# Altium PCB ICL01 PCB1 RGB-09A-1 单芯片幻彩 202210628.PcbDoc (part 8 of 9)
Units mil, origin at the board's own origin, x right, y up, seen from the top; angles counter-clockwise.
Board outline 17436.43 x 6581.89 mil, 2 copper layers (Top Layer, Bottom Layer), stack 65.792 mil thick; 425 components, 516 nets, 1625 pads, 2772 vias.
Unrouted connection lines stored in the file: 1.
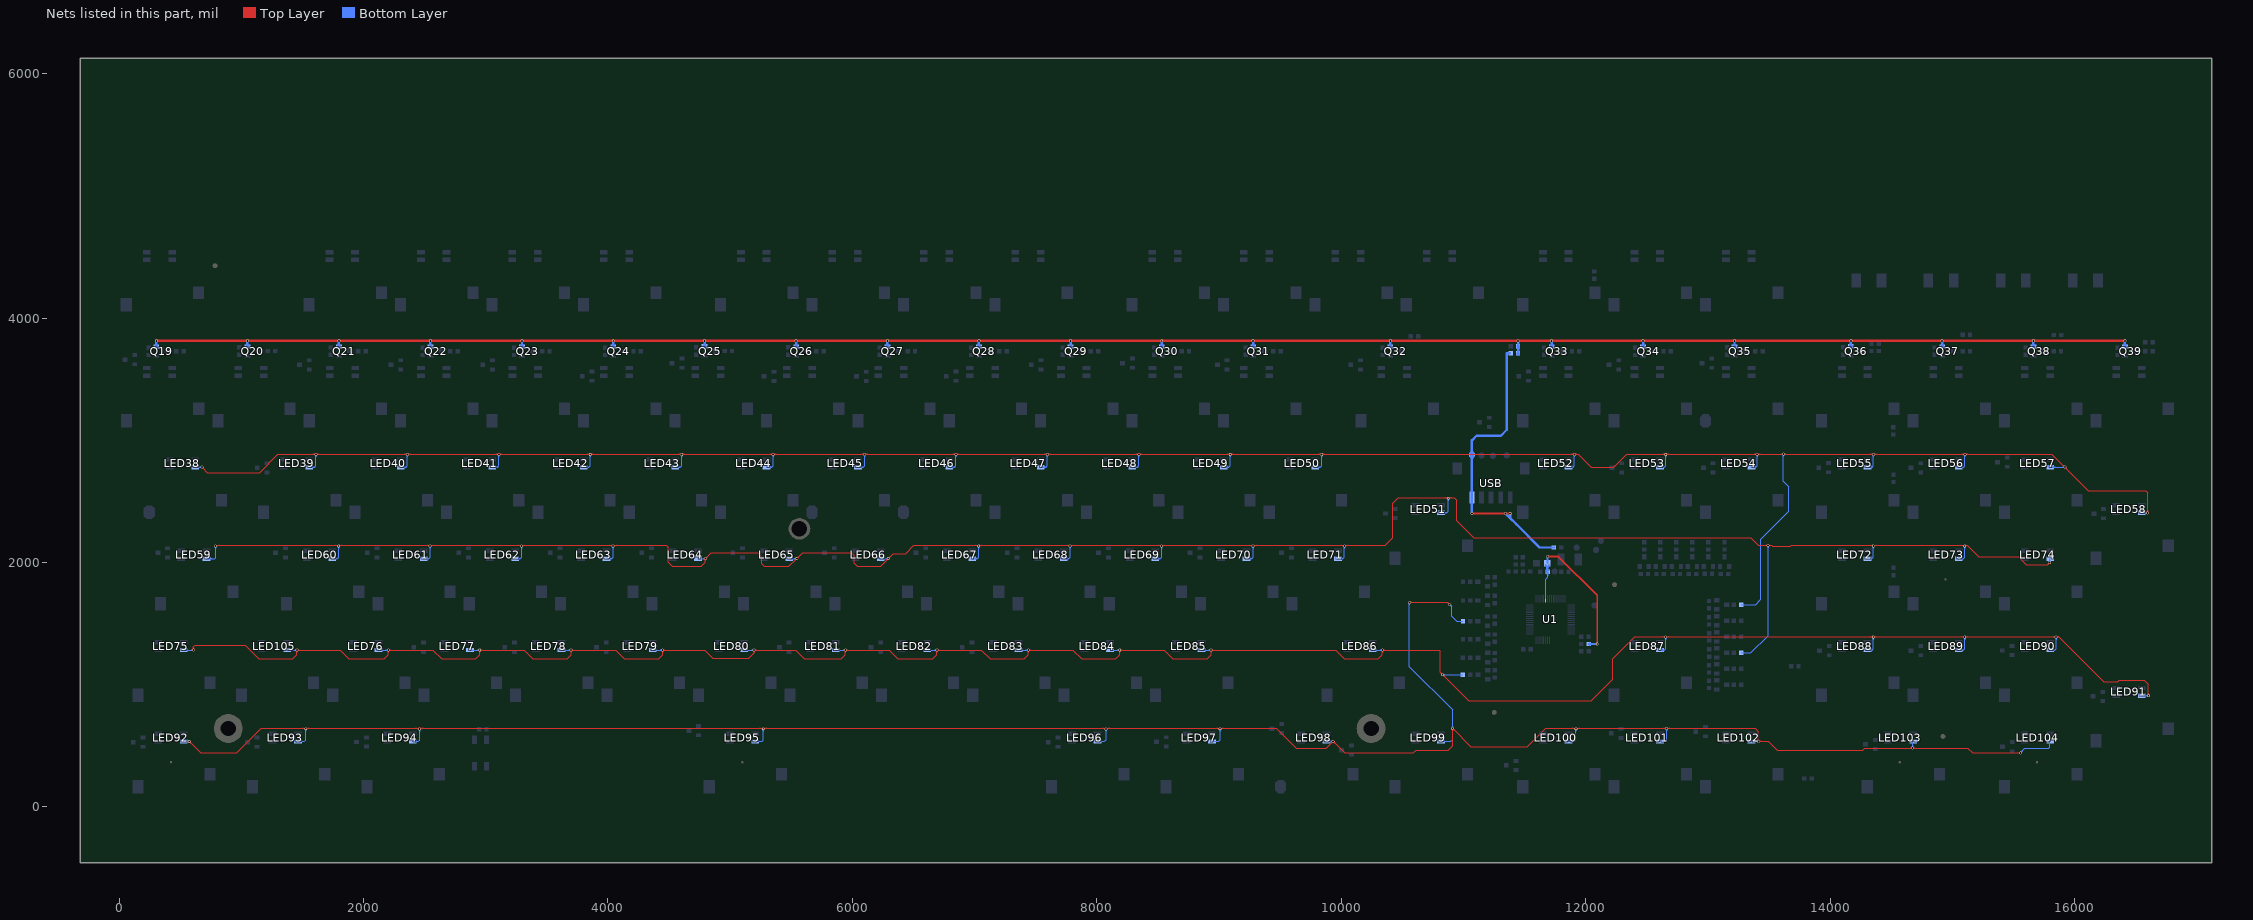
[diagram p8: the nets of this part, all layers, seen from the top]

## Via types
v1: diameter 23.62, hole 15.75, Top Layer to Bottom Layer, tented both sides, 2766 vias
v2: diameter 19.68, hole 11.81, Top Layer to Bottom Layer, tented both sides, 6 vias

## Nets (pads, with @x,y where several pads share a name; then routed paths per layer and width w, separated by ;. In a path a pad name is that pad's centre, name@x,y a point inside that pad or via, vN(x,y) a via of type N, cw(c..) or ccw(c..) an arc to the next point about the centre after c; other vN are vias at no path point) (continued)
RED2: LED38.R LED39.R LED40.R LED41.R LED42.R LED43.R LED44.R LED45.R LED46.R LED47.R LED48.R LED49.R LED50.R LED52.R LED53.R LED54.R LED55.R LED56.R LED57.R LED58.R RR7.2 | length 23323.4
  Top Layer w7.87: v1@680.32,2771.85 cw(c680.32,2752.84) 693.77,2766.28 cw(c707.21,2779.73) v1@688.2,2779.73 ; v1(680.32,2779.73) 723.96,2736.09 1149.71,2736.09 1300.78,2887.16 v1@11906.84,2887.16 ; 1587.12,2887.16 cw(c1587.12,2860.47) v1@1605.99,2879.34 ; 1597.98,2887.16 ccw(c1597.98,2898.49) v1@1605.99,2890.48 ; v1@1617.13,2879.34 cw(c1636,2860.47) 1636,2887.16 ; v1@1617.13,2890.48 ccw(c1625.14,2898.49) 1625.14,2887.16 ; 2335.15,2887.16 cw(c2335.15,2860.47) v1@2354.03,2879.34 ; 2346.01,2887.16 ccw(c2346.01,2898.49) v1@2354.03,2890.48 ; v1@2365.16,2879.34 cw(c2384.03,2860.47) 2384.03,2887.16 ; v1@2365.16,2890.48 ccw(c2373.17,2898.49) 2373.17,2887.16 ; 3083.18,2887.16 cw(c3083.18,2860.47) v1@3102.06,2879.34 ; 3094.05,2887.16 ccw(c3094.05,2898.49) v1@3102.06,2890.48 ; v1@3113.19,2879.34 cw(c3132.06,2860.47) 3132.06,2887.16 ; v1@3113.19,2890.48 ccw(c3121.2,2898.49) 3121.2,2887.16 ; 3831.22,2887.16 cw(c3831.22,2860.47) v1@3850.09,2879.34 ; 3842.08,2887.16 ccw(c3842.08,2898.49) v1@3850.09,2890.48 ; v1@3861.22,2879.34 cw(c3880.1,2860.47) 3880.1,2887.16 ; v1@3861.22,2890.48 ccw(c3869.23,2898.49) 3869.23,2887.16 ; 4579.25,2887.16 cw(c4579.25,2860.47) v1@4598.12,2879.34 ; 4590.11,2887.16 ccw(c4590.11,2898.49) v1@4598.12,2890.48 ; v1@4609.26,2879.34 cw(c4628.13,2860.47) 4628.13,2887.16 ; v1@4609.26,2890.48 ccw(c4617.27,2898.49) 4617.27,2887.16 ; 5327.28,2887.16 cw(c5327.28,2860.47) v1@5346.15,2879.34 ; 5338.14,2887.16 ccw(c5338.14,2898.49) v1@5346.15,2890.48 ; v1@5357.29,2879.34 cw(c5376.16,2860.47) 5376.16,2887.16 ; v1@5357.29,2890.48 ccw(c5365.3,2898.49) 5365.3,2887.16 ; 6075.31,2887.16 cw(c6075.31,2860.47) v1@6094.18,2879.34 ; 6086.17,2887.16 ccw(c6086.17,2898.49) v1@6094.18,2890.48 ; v1@6105.32,2879.34 cw(c6124.19,2860.47) 6124.19,2887.16 ; v1@6105.32,2890.48 ccw(c6113.33,2898.49) 6113.33,2887.16 ; 6823.34,2887.16 cw(c6823.34,2860.47) v1@6842.21,2879.34 ; 6834.2,2887.16 ccw(c6834.2,2898.49) v1@6842.21,2890.48 ; v1@6853.35,2879.34 cw(c6872.22,2860.47) 6872.22,2887.16 ; v1@6853.35,2890.48 ccw(c6861.36,2898.49) 6861.36,2887.16 ; 7571.37,2887.16 cw(c7571.37,2860.47) v1@7590.25,2879.34 ; 7582.23,2887.16 ccw(c7582.23,2898.49) v1@7590.25,2890.48 ; v1@7601.38,2879.34 cw(c7620.25,2860.47) 7620.25,2887.16 ; v1@7601.38,2890.48 ccw(c7609.39,2898.49) 7609.39,2887.16 ; 8319.4,2887.16 cw(c8319.4,2860.47) v1@8338.28,2879.34 ; 8330.27,2887.16 ccw(c8330.27,2898.49) v1@8338.28,2890.48 ; v1@8349.41,2879.34 cw(c8368.29,2860.47) 8368.29,2887.16 ; v1@8349.41,2890.48 ccw(c8357.42,2898.49) 8357.42,2887.16 ; 9067.44,2887.16 cw(c9067.44,2860.47) v1@9086.31,2879.34 ; 9078.3,2887.16 ccw(c9078.3,2898.49) v1@9086.31,2890.48 ; v1@9097.44,2879.34 cw(c9116.32,2860.47) 9116.32,2887.16 ; v1@9097.44,2890.48 ccw(c9105.45,2898.49) 9105.45,2887.16 ; 9815.47,2887.16 cw(c9815.47,2860.47) v1@9834.34,2879.34 ; 9826.33,2887.16 ccw(c9826.33,2898.49) v1@9834.34,2890.48 ; v1@9845.48,2879.34 cw(c9864.35,2860.47) 9864.35,2887.16 ; v1@9845.48,2890.48 ccw(c9853.49,2898.49) 9853.49,2887.16 ; 11882.4,2887.16 cw(c11882.4,2860.47) v1@11901.27,2879.34 ; 11893.26,2887.16 ccw(c11893.26,2898.49) v1@11901.27,2890.48 ; v1(11906.84,2884.91) 11939.02,2884.91 12045.44,2778.49 12227.84,2778.49 12336.5,2887.16 13617.79,2887.16 v1(13618.05,2886.9) 15813.44,2886.9 v1@15920.65,2779.69 ; v1@11912.41,2879.34 cw(c11925.85,2865.9) 11925.85,2884.91 cw(c11925.85,2903.92) v1@11912.41,2890.48 ; 12630.43,2887.16 cw(c12630.43,2860.47) v1@12649.3,2879.34 ; 12641.29,2887.16 ccw(c12641.29,2898.49) v1@12649.3,2890.48 ; v1@12660.44,2879.34 cw(c12679.31,2860.47) 12679.31,2887.16 ; v1@12660.44,2890.48 ccw(c12668.45,2898.49) 12668.45,2887.16 ; 13378.46,2887.16 cw(c13378.46,2860.47) v1@13397.33,2879.34 ; 13389.32,2887.16 ccw(c13389.32,2898.49) v1@13397.33,2890.48 ; v1@13408.47,2879.34 cw(c13427.34,2860.47) 13427.34,2887.16 ; v1@13408.47,2890.48 ccw(c13416.48,2898.49) 13416.48,2887.16 ; 13598.42,2887.16 cw(c13598.42,2867.28) v1@13612.48,2881.34 ; 13599.66,2887.16 ccw(c13599.66,2905.3) v1@13612.48,2892.47 ; v1@13623.62,2881.34 cw(c13637.06,2867.89) 13637.06,2886.9 cw(c13637.06,2905.91) v1@13623.62,2892.47 ; 14329.86,2886.9 cw(c14329.86,2861.09) v1@14348.12,2879.34 ; 14339.49,2886.9 ccw(c14339.49,2899.1) v1@14348.12,2890.48 ; v1@14359.26,2879.34 cw(c14377.51,2861.09) 14377.51,2886.9 ; v1@14359.26,2890.48 ccw(c14367.88,2899.1) 14367.88,2886.9 ; 15077.9,2886.9 cw(c15077.9,2861.09) v1@15096.15,2879.34 ; 15087.52,2886.9 ccw(c15087.52,2899.1) v1@15096.15,2890.48 ; v1@15107.29,2879.34 cw(c15125.54,2861.09) 15125.54,2886.9 ; v1@15107.29,2890.48 ccw(c15115.91,2899.1) 15115.91,2886.9 ; 15907.13,2793.21 ccw(c15920.68,2806.77) v1@15920.68,2787.6 ; 15907.29,2793.06 cw(c15893.96,2779.73) v1@15912.81,2779.73 ; v1@15920.68,2771.85 cw(c15920.68,2752.84) 15934.12,2766.28 cw(c15947.57,2779.73) v1@15928.56,2779.73 ; v1(15920.68,2779.73) 16112.05,2588.35 16580.42,2588.35 16596.64,2572.13 v1@16596.64,2405.71 ; v1@16591.15,2411.28 ccw(c16577.91,2424.53) 16596.64,2424.53 ; 16596.64,2424.91 ccw(c16615.92,2424.91) v1@16602.29,2411.28
  Bottom Layer w7.87: LED38.R@622.66,2779.73 v1(680.32,2779.73) ; v1@674.76,2774.16 ccw(c661.31,2760.72) 661.31,2779.73 ccw(c661.31,2798.74) v1@674.76,2785.29 ; LED39.R@1557.7,2779.73 1600.85,2779.73 ; LED39.R@1582.08,2770.92 cw(c1600.85,2755.31) 1600.85,2779.73 ; LED39.R@1582.08,2788.53 ccw(c1600.85,2804.14) 1600.85,2779.73 ; v1@1605.99,2879.34 cw(c1592.58,2865.93) 1611.55,2865.93 ; 1611.55,2865.87 cw(c1630.6,2865.87) v1@1617.13,2879.34 ; v1@1611.55,2886.39 1611.55,2790.42 1600.85,2779.73 ; LED40.R@2305.73,2779.73 2348.89,2779.73 ; LED40.R@2330.11,2770.92 cw(c2348.88,2755.31) 2348.88,2779.73 ; LED40.R@2330.11,2788.53 ccw(c2348.88,2804.14) 2348.88,2779.73 ; v1@2354.03,2879.34 cw(c2340.61,2865.93) 2359.58,2865.93 ; 2359.58,2865.87 cw(c2378.63,2865.87) v1@2365.16,2879.34 ; v1@2359.58,2886.39 2359.58,2790.42 2348.89,2779.73 ; LED41.R@3053.76,2779.73 3096.92,2779.73 ; LED41.R@3078.14,2770.92 cw(c3096.92,2755.31) 3096.92,2779.73 ; LED41.R@3078.14,2788.53 ccw(c3096.92,2804.14) 3096.92,2779.73 ; v1@3102.06,2879.34 cw(c3088.65,2865.93) 3107.61,2865.93 ; 3107.61,2865.87 cw(c3126.66,2865.87) v1@3113.19,2879.34 ; v1@3107.61,2886.39 3107.61,2790.42 3096.92,2779.73 ; LED42.R@3801.8,2779.73 3844.95,2779.73 ; LED42.R@3826.17,2770.92 cw(c3844.95,2755.31) 3844.95,2779.73 ; LED42.R@3826.17,2788.53 ccw(c3844.95,2804.14) 3844.95,2779.73 ; v1@3850.09,2879.34 cw(c3836.68,2865.93) 3855.64,2865.93 ; 3855.64,2865.87 cw(c3874.7,2865.87) v1@3861.22,2879.34 ; v1@3855.64,2886.39 3855.64,2790.42 3844.95,2779.73 ; LED43.R@4549.83,2779.73 4592.98,2779.73 ; LED43.R@4574.2,2770.92 cw(c4592.98,2755.31) 4592.98,2779.73 ; LED43.R@4574.2,2788.53 ccw(c4592.98,2804.14) 4592.98,2779.73 ; v1@4598.12,2879.34 cw(c4584.71,2865.93) 4603.67,2865.93 ; 4603.67,2865.87 cw(c4622.73,2865.87) v1@4609.26,2879.34 ; v1@4603.67,2886.39 4603.67,2790.42 4592.98,2779.73 ; LED44.R@5297.86,2779.73 5341.01,2779.73 ; LED44.R@5322.23,2770.92 cw(c5341.01,2755.31) 5341.01,2779.73 ; LED44.R@5322.23,2788.53 ccw(c5341.01,2804.14) 5341.01,2779.73 ; v1@5346.15,2879.34 cw(c5332.74,2865.93) 5351.71,2865.93 ; 5351.71,2865.87 cw(c5370.76,2865.87) v1@5357.29,2879.34 ; v1@5351.71,2886.39 5351.71,2790.42 5341.01,2779.73 ; LED45.R@6045.89,2779.73 6089.04,2779.73 ; LED45.R@6070.27,2770.92 cw(c6089.04,2755.31) 6089.04,2779.73 ; LED45.R@6070.27,2788.53 ccw(c6089.04,2804.14) 6089.04,2779.73 ; v1@6094.18,2879.34 cw(c6080.77,2865.93) 6099.74,2865.93 ; 6099.74,2865.87 cw(c6118.79,2865.87) v1@6105.32,2879.34 ; v1@6099.74,2886.39 6099.74,2790.42 6089.04,2779.73 ; LED46.R@6793.92,2779.73 6837.08,2779.73 ; LED46.R@6818.3,2770.92 cw(c6837.07,2755.31) 6837.07,2779.73 ; LED46.R@6818.3,2788.53 ccw(c6837.07,2804.14) 6837.07,2779.73 ; v1@6842.21,2879.34 cw(c6828.8,2865.93) 6847.77,2865.93 ; 6847.77,2865.87 cw(c6866.82,2865.87) v1@6853.35,2879.34 ; v1@6847.77,2886.39 6847.77,2790.42 6837.08,2779.73 ; LED47.R@7541.95,2779.73 7585.11,2779.73 ; LED47.R@7566.33,2770.92 cw(c7585.1,2755.31) 7585.1,2779.73 ; LED47.R@7566.33,2788.53 ccw(c7585.1,2804.14) 7585.1,2779.73 ; v1@7590.25,2879.34 cw(c7576.83,2865.93) 7595.8,2865.93 ; 7595.8,2865.87 cw(c7614.85,2865.87) v1@7601.38,2879.34 ; v1@7595.8,2886.39 7595.8,2790.42 7585.11,2779.73 ; LED48.R@8289.98,2779.73 8333.14,2779.73 ; LED48.R@8314.36,2770.92 cw(c8333.14,2755.31) 8333.14,2779.73 ; LED48.R@8314.36,2788.53 ccw(c8333.14,2804.14) 8333.14,2779.73 ; v1@8338.28,2879.34 cw(c8324.87,2865.93) 8343.83,2865.93 ; 8343.83,2865.87 cw(c8362.89,2865.87) v1@8349.41,2879.34 ; v1@8343.83,2886.39 8343.83,2790.42 8333.14,2779.73 ; LED49.R@9038.02,2779.73 9081.17,2779.73 ; LED49.R@9062.39,2770.92 cw(c9081.17,2755.31) 9081.17,2779.73 ; LED49.R@9062.39,2788.53 ccw(c9081.17,2804.14) 9081.17,2779.73 ; v1@9086.31,2879.34 cw(c9072.9,2865.93) 9091.86,2865.93 ; 9091.86,2865.87 cw(c9110.92,2865.87) v1@9097.44,2879.34 ; v1@9091.86,2886.39 9091.86,2790.42 9081.17,2779.73 ; LED50.R@9786.05,2779.73 9829.2,2779.73 ; LED50.R@9810.42,2770.92 cw(c9829.2,2755.31) 9829.2,2779.73 ; LED50.R@9810.42,2788.53 ccw(c9829.2,2804.14) 9829.2,2779.73 ; v1@9834.34,2879.34 cw(c9820.93,2865.93) 9839.9,2865.93 ; 9839.9,2865.87 cw(c9858.95,2865.87) v1@9845.48,2879.34 ; v1@9839.9,2886.39 9839.9,2790.42 9829.2,2779.73 ; LED52.R@11852.98,2779.73 11896.13,2779.73 11906.82,2790.42 v1@11906.82,2886.39 ; LED52.R@11877.35,2770.92 cw(c11896.13,2755.31) 11896.13,2779.73 cw(c11896.13,2804.14) LED52.R@11877.35,2788.53 ; v1@11901.27,2879.34 cw(c11887.86,2865.93) 11906.82,2865.93 ; 11906.82,2865.87 cw(c11925.88,2865.87) v1@11912.41,2879.34 ; LED53.R@12601.01,2779.73 12644.16,2779.73 ; LED53.R@12625.38,2770.92 cw(c12644.16,2755.31) 12644.16,2779.73 ; LED53.R@12625.38,2788.53 ccw(c12644.16,2804.14) 12644.16,2779.73 ; v1@12649.3,2879.34 cw(c12635.89,2865.93) 12654.86,2865.93 ; 12654.86,2865.87 cw(c12673.91,2865.87) v1@12660.44,2879.34 ; v1@12654.86,2886.39 12654.86,2790.42 12644.16,2779.73 ; RR7.2@13272.34,1654.53 13389.47,1654.53 13433.74,1698.79 13433.74,2190.36 13662.06,2418.68 13662.06,2619.52 13617.79,2663.79 v1@13617.79,2887.16 ; LED54.R@13349.04,2779.73 13392.19,2779.73 ; LED54.R@13373.42,2770.92 cw(c13392.19,2755.31) 13392.19,2779.73 ; LED54.R@13373.42,2788.53 ccw(c13392.19,2804.14) 13392.19,2779.73 ; v1@13397.33,2879.34 cw(c13383.92,2865.93) 13402.89,2865.93 ; 13402.89,2865.87 cw(c13421.94,2865.87) v1@13408.47,2879.34 ; v1@13402.89,2886.39 13402.89,2790.42 13392.19,2779.73 ; v1@13612.48,2881.34 cw(c13599.66,2868.51) 13617.79,2868.51 ; 13617.79,2867.28 cw(c13637.68,2867.28) v1@13623.62,2881.34 ; LED55.R@14299.83,2779.73 14342.98,2779.73 ; LED55.R@14324.2,2770.92 cw(c14342.98,2755.31) 14342.98,2779.73 ; LED55.R@14324.2,2788.53 ccw(c14342.98,2804.14) 14342.98,2779.73 ; v1@14348.12,2879.34 cw(c14334.71,2865.93) 14353.67,2865.93 ; 14353.67,2865.87 cw(c14372.73,2865.87) v1@14359.26,2879.34 ; v1@14353.67,2886.39 14353.67,2790.42 14342.98,2779.73 ; LED56.R@15047.86,2779.73 15091.01,2779.73 ; LED56.R@15072.23,2770.92 cw(c15091.01,2755.31) 15091.01,2779.73 ; LED56.R@15072.23,2788.53 ccw(c15091.01,2804.14) 15091.01,2779.73 ; v1@15096.15,2879.34 cw(c15082.74,2865.93) 15101.71,2865.93 ; 15101.71,2865.87 cw(c15120.76,2865.87) v1@15107.29,2879.34 ; v1@15101.71,2886.39 15101.71,2790.42 15091.01,2779.73 ; LED57.R@15795.89,2779.73 v1(15920.68,2779.73) ; LED57.R@15819.41,2769.98 cw(c15842.94,2746.46) 15842.94,2779.73 cw(c15842.94,2812.99) LED57.R@15819.41,2789.47 ; v1@15915.11,2774.16 ccw(c15901.67,2760.72) 15901.67,2779.73 ccw(c15901.67,2798.74) v1@15915.11,2785.29 ; LED58.R@16543.92,2405.71 v1(16596.72,2405.71) ; v1@16591.15,2400.14 ccw(c16577.71,2386.7) 16577.71,2405.71 ccw(c16577.71,2424.72) v1@16591.15,2411.28
  other v1: 1611.56,2884.91 2359.59,2884.91 3107.62,2884.91 3855.66,2884.91 4603.69,2884.91 5351.72,2884.91 6099.75,2884.91 6847.78,2884.91 7595.81,2884.91 8343.85,2884.91 9091.88,2884.91 9839.91,2884.91 12654.87,2884.91 13402.9,2884.91 14353.69,2884.91 15101.72,2884.91
RED3: LED51.R LED59.R LED60.R LED61.R LED62.R LED63.R LED64.R LED65.R LED66.R LED67.R LED68.R LED69.R LED70.R LED71.R LED72.R LED73.R LED74.R RR10.2 | length 21455.8
  Top Layer w7.87: v1@789.66,2139.13 4477.62,2139.13 4493.78,2122.96 4493.78,2001.99 4528.32,1967.45 4761.99,1967.45 4797.42,2002.87 v1(4797.42,2031.69) 4846.54,2080.81 5227.15,2080.81 5259.88,2048.09 5259.88,1990.35 5280.85,1969.37 5481.29,1969.37 5543.61,2031.69 v1(5545.45,2031.69) 5594.57,2080.81 5996.2,2080.81 6016.98,2060.03 6016.98,1993.92 6039.89,1971 6232.79,1971 v1(6293.48,2031.69) 6335.1,2073.31 6436.21,2073.31 6502.03,2139.13 10358.78,2139.13 10420.83,2201.17 10420.83,2485.52 10465.24,2529.93 10923.17,2529.93 10944.09,2509.01 10944.09,2342.39 11083.27,2203.2 13348.91,2203.2 13412.98,2139.13 v1(13491.81,2139.13) 13520.28,2139.13 13526.56,2132.85 13675.97,2132.85 13682.25,2139.13 15123.24,2139.13 ; v1@795.23,2129.51 cw(c818.45,2106.28) 818.45,2139.13 ; 1772.04,2139.13 cw(c1772.04,2110.59) v1@1792.23,2130.77 ; 1785.52,2139.13 ccw(c1785.52,2148.61) v1@1792.23,2141.9 ; v1@1803.36,2130.77 cw(c1823.54,2110.59) 1823.54,2139.13 ; v1@1803.36,2141.9 ccw(c1810.06,2148.61) 1810.06,2139.13 ; 2520.08,2139.13 cw(c2520.08,2110.59) v1@2540.26,2130.77 ; 2533.55,2139.13 ccw(c2533.55,2148.61) v1@2540.26,2141.9 ; v1@2551.39,2130.77 cw(c2571.57,2110.59) 2571.57,2139.13 ; v1@2551.39,2141.9 ccw(c2558.1,2148.61) 2558.1,2139.13 ; 3268.11,2139.13 cw(c3268.11,2110.59) v1@3288.29,2130.77 ; 3281.59,2139.13 ccw(c3281.59,2148.61) v1@3288.29,2141.9 ; v1@3299.42,2130.77 cw(c3319.6,2110.59) 3319.6,2139.13 ; v1@3299.42,2141.9 ccw(c3306.13,2148.61) 3306.13,2139.13 ; 4016.14,2139.13 cw(c4016.14,2110.59) v1@4036.32,2130.77 ; 4029.62,2139.13 ccw(c4029.62,2148.61) v1@4036.32,2141.9 ; v1@4047.46,2130.77 cw(c4067.64,2110.59) 4067.64,2139.13 ; v1@4047.46,2141.9 ccw(c4054.16,2148.61) 4054.16,2139.13 ; v1@4791.85,2026.13 cw(c4778.41,2012.69) 4797.42,2012.69 cw(c4816.43,2012.69) v1@4802.99,2026.13 ; v1@4797.42,2039.57 ccw(c4797.42,2058.58) 4810.86,2045.14 ccw(c4824.3,2031.69) v1@4805.29,2031.69 ; 5528.87,2016.95 cw(c5545.45,2000.37) v1@5545.45,2023.82 ; 5533.31,2021.39 ccw(c5523.01,2031.69) v1@5537.58,2031.69 ; v1@5545.45,2039.57 ccw(c5545.45,2058.58) 5558.89,2045.14 ccw(c5572.34,2031.69) v1@5553.33,2031.69 ; v1@6285.61,2031.69 cw(c6266.6,2031.69) 6280.04,2018.25 cw(c6293.48,2004.81) v1@6293.48,2023.82 ; v1@6293.48,2039.57 ccw(c6293.48,2058.58) 6306.93,2045.14 ccw(c6320.37,2031.69) v1@6301.36,2031.69 ; 7008.27,2139.13 cw(c7008.27,2110.59) v1@7028.45,2130.77 ; 7021.74,2139.13 ccw(c7021.74,2148.61) v1@7028.45,2141.9 ; v1@7039.58,2130.77 cw(c7059.76,2110.59) 7059.76,2139.13 ; v1@7039.58,2141.9 ccw(c7046.28,2148.61) 7046.28,2139.13 ; 7756.3,2139.13 cw(c7756.3,2110.59) v1@7776.48,2130.77 ; 7769.77,2139.13 ccw(c7769.77,2148.61) v1@7776.48,2141.9 ; v1@7787.61,2130.77 cw(c7807.79,2110.59) 7807.79,2139.13 ; v1@7787.61,2141.9 ccw(c7794.32,2148.61) 7794.32,2139.13 ; 8504.33,2139.13 cw(c8504.33,2110.59) v1@8524.51,2130.77 ; 8517.81,2139.13 ccw(c8517.81,2148.61) v1@8524.51,2141.9 ; v1@8535.64,2130.77 cw(c8555.83,2110.59) 8555.83,2139.13 ; v1@8535.64,2141.9 ccw(c8542.35,2148.61) 8542.35,2139.13 ; 9252.36,2139.13 cw(c9252.36,2110.59) v1@9272.54,2130.77 ; 9265.84,2139.13 ccw(c9265.84,2148.61) v1@9272.54,2141.9 ; v1@9283.68,2130.77 cw(c9303.86,2110.59) 9303.86,2139.13 ; v1@9283.68,2141.9 ccw(c9290.38,2148.61) 9290.38,2139.13 ; 10000.39,2139.13 cw(c10000.39,2110.59) v1@10020.57,2130.77 ; 10013.87,2139.13 ccw(c10013.87,2148.61) v1@10020.57,2141.9 ; v1@10031.71,2130.77 cw(c10051.89,2110.59) 10051.89,2139.13 ; v1@10031.71,2141.9 ccw(c10038.41,2148.61) 10038.41,2139.13 ; 10845.6,2529.93 cw(c10845.6,2495.65) v1@10869.84,2519.89 ; v1@10880.97,2519.89 cw(c10905.21,2495.65) 10905.21,2529.93 ; v1@13486.24,2133.56 ccw(c13472.8,2120.12) 13472.8,2139.13 ccw(c13472.8,2158.14) v1@13486.24,2144.7 ; v1@13497.38,2133.56 cw(c13510.82,2120.12) 13510.82,2139.13 cw(c13510.82,2158.14) v1@13497.38,2144.7 ; 14327.16,2139.13 cw(c14327.16,2110.59) v1@14347.34,2130.77 ; 14340.64,2139.13 ccw(c14340.64,2148.61) v1@14347.34,2141.9 ; v1@14358.48,2130.77 cw(c14378.66,2110.59) 14378.66,2139.13 ; v1@14358.48,2141.9 ccw(c14365.18,2148.61) 14365.18,2139.13 ; 15075.19,2139.13 cw(c15075.19,2110.59) v1@15095.38,2130.77 ; 15088.67,2139.13 ccw(c15088.67,2148.61) v1@15095.38,2141.9 ; v1@15106.51,2141.9 ccw(c15113.21,2148.61) 15113.21,2139.13 ; v1@15107.07,2131.39 cw(c15123.24,2118.36) 15123.24,2139.13 ; v1@15788.29,1998.96 cw(c15769.29,1998.96) 15782.73,1985.52 cw(c15796.17,1972.08) v1@15796.17,1991.09 ; v1(15796.17,1998.96) 15778.36,1981.16 15604.32,1981.16 15539.06,2046.42 15215.95,2046.42 15123.24,2139.13
  Bottom Layer w7.87: LED59.R@716.17,2031.69 781.7,2031.69 789.66,2039.65 v1(789.66,2135.07) ; LED59.R@739.69,2021.95 cw(c763.21,1998.43) 763.21,2031.69 cw(c763.21,2064.96) LED59.R@739.69,2041.44 ; v1@784.09,2129.51 cw(c770.65,2116.07) 789.66,2116.07 cw(c808.67,2116.07) v1@795.23,2129.51 ; LED60.R@1744.71,2031.69 1785.35,2031.69 ; LED60.R@1769.68,2023.66 cw(c1785.35,2012.41) 1785.35,2031.69 ; LED60.R@1769.68,2039.73 ccw(c1785.35,2050.98) 1785.35,2031.69 ; v1@1792.23,2130.77 cw(c1778.88,2117.42) 1797.75,2117.42 ; 1797.75,2117.23 cw(c1816.9,2117.23) v1@1803.36,2130.77 ; v1@1797.75,2138.36 1797.75,2044.1 1785.35,2031.69 ; LED61.R@2492.74,2031.69 2533.38,2031.69 2545.79,2044.1 v1@2545.79,2138.36 ; LED61.R@2517.71,2023.66 cw(c2533.38,2012.41) 2533.38,2031.69 cw(c2533.38,2050.98) LED61.R@2517.71,2039.73 ; v1@2540.26,2130.77 cw(c2526.91,2117.42) 2545.79,2117.42 ; 2545.79,2117.23 cw(c2564.93,2117.23) v1@2551.39,2130.77 ; LED62.R@3240.77,2031.69 3281.41,2031.69 ; LED62.R@3265.74,2023.66 cw(c3281.41,2012.41) 3281.41,2031.69 ; LED62.R@3265.74,2039.73 ccw(c3281.41,2050.98) 3281.41,2031.69 ; v1@3288.29,2130.77 cw(c3274.94,2117.42) 3293.82,2117.42 ; 3293.82,2117.23 cw(c3312.96,2117.23) v1@3299.42,2130.77 ; v1@3293.82,2138.36 3293.82,2044.1 3281.41,2031.69 ; LED63.R@3988.8,2031.69 4029.44,2031.69 ; LED63.R@4013.78,2023.66 cw(c4029.44,2012.41) 4029.44,2031.69 ; LED63.R@4013.78,2039.73 ccw(c4029.44,2050.98) 4029.44,2031.69 ; v1@4036.32,2130.77 cw(c4022.97,2117.42) 4041.85,2117.42 ; 4041.85,2117.23 cw(c4060.99,2117.23) v1@4047.46,2130.77 ; v1@4041.85,2138.36 4041.85,2044.1 4029.44,2031.69 ; LED64.R@4736.83,2031.69 v1(4797.42,2031.69) ; v1@4791.85,2026.13 ccw(c4778.41,2012.69) 4778.41,2031.69 ccw(c4778.41,2050.7) v1@4791.85,2037.26 ; LED65.R@5484.87,2031.69 v1(5545.45,2031.69) ; v1@5539.88,2026.13 ccw(c5526.44,2012.69) 5526.44,2031.69 ccw(c5526.44,2050.7) v1@5539.88,2037.26 ; LED66.R@6232.9,2031.69 v1(6293.48,2031.69) ; v1@6287.92,2026.13 ccw(c6274.47,2012.69) 6274.47,2031.69 ccw(c6274.47,2050.7) v1@6287.92,2037.26 ; LED67.R@6980.93,2031.69 7021.57,2031.69 ; LED67.R@7005.9,2023.66 cw(c7021.57,2012.41) 7021.57,2031.69 ; LED67.R@7005.9,2039.73 ccw(c7021.57,2050.98) 7021.57,2031.69 ; v1@7028.45,2130.77 cw(c7015.1,2117.42) 7033.97,2117.42 ; 7033.97,2117.23 cw(c7053.12,2117.23) v1@7039.58,2130.77 ; v1@7033.97,2138.36 7033.97,2044.1 7021.57,2031.69 ; LED68.R@7728.96,2031.69 7769.6,2031.69 ; LED68.R@7753.93,2023.66 cw(c7769.6,2012.41) 7769.6,2031.69 ; LED68.R@7753.93,2039.73 ccw(c7769.6,2050.98) 7769.6,2031.69 ; v1@7776.48,2130.77 cw(c7763.13,2117.42) 7782.01,2117.42 ; 7782.01,2117.23 cw(c7801.15,2117.23) v1@7787.61,2130.77 ; v1@7782.01,2138.36 7782.01,2044.1 7769.6,2031.69 ; LED69.R@8476.99,2031.69 8517.63,2031.69 ; LED69.R@8501.97,2023.66 cw(c8517.63,2012.41) 8517.63,2031.69 ; LED69.R@8501.97,2039.73 ccw(c8517.63,2050.98) 8517.63,2031.69 ; v1@8524.51,2130.77 cw(c8511.16,2117.42) 8530.04,2117.42 ; 8530.04,2117.23 cw(c8549.18,2117.23) v1@8535.64,2130.77 ; v1@8530.04,2138.36 8530.04,2044.1 8517.63,2031.69 ; LED70.R@9225.02,2031.69 9265.66,2031.69 ; LED70.R@9250,2023.66 cw(c9265.66,2012.41) 9265.66,2031.69 ; LED70.R@9250,2039.73 ccw(c9265.66,2050.98) 9265.66,2031.69 ; v1@9272.54,2130.77 cw(c9259.19,2117.42) 9278.07,2117.42 ; 9278.07,2117.23 cw(c9297.21,2117.23) v1@9283.68,2130.77 ; v1@9278.07,2138.36 9278.07,2044.1 9265.66,2031.69 ; LED71.R@9973.06,2031.69 10013.69,2031.69 ; LED71.R@9998.03,2023.66 cw(c10013.69,2012.41) 10013.69,2031.69 ; LED71.R@9998.03,2039.73 ccw(c10013.69,2050.98) 10013.69,2031.69 ; v1@10020.57,2130.77 cw(c10007.23,2117.42) 10026.1,2117.42 ; 10026.1,2117.23 cw(c10045.24,2117.23) v1@10031.71,2130.77 ; v1@10026.1,2138.36 10026.1,2044.1 10013.69,2031.69 ; LED51.R@10814.15,2405.65 10861.21,2405.65 ; LED51.R@10837.67,2395.91 cw(c10861.2,2372.38) 10861.2,2405.65 ; LED51.R@10837.67,2415.39 ccw(c10861.2,2438.92) 10861.2,2405.65 ; v1@10869.84,2519.89 cw(c10856.4,2506.45) 10875.41,2506.45 cw(c10894.41,2506.45) v1@10880.97,2519.89 ; v1(10875.41,2525.46) 10875.41,2419.84 10861.21,2405.65 ; RR10.2@13272.34,1260.35 13351.2,1260.35 13491.81,1400.95 v1(13491.81,2139.13) ; v1@13486.24,2133.56 cw(c13472.8,2120.12) 13491.81,2120.12 cw(c13510.82,2120.12) v1@13497.38,2133.56 ; LED72.R@14299.83,2031.69 14340.47,2031.69 ; LED72.R@14324.8,2023.66 cw(c14340.46,2012.41) 14340.46,2031.69 ; LED72.R@14324.8,2039.73 ccw(c14340.46,2050.98) 14340.46,2031.69 ; v1@14347.34,2130.77 cw(c14334,2117.42) 14352.87,2117.42 ; 14352.87,2117.23 cw(c14372.02,2117.23) v1@14358.48,2130.77 ; v1@14352.87,2138.36 14352.87,2044.1 14340.47,2031.69 ; LED73.R@15047.86,2031.69 15088.5,2031.69 ; LED73.R@15072.83,2023.66 cw(c15088.5,2012.41) 15088.5,2031.69 ; LED73.R@15072.83,2039.73 ccw(c15088.5,2050.98) 15088.5,2031.69 ; v1@15095.38,2130.77 cw(c15082.03,2117.42) 15100.9,2117.42 ; 15100.9,2117.23 cw(c15120.05,2117.23) v1@15106.51,2130.77 ; v1@15100.9,2138.36 15100.9,2044.1 15088.5,2031.69 ; v1@15790.6,2004.53 ccw(c15777.83,2017.3) LED74.R@15795.89,2017.3 ; v1@15795.89,1999.24 LED74.R@15795.89,2031.69 ; LED74.R@15795.89,2018.65 ccw(c15815.85,2018.65) v1@15801.74,2004.53
  other v1: 1797.79,2136.34 2545.83,2136.34 3293.86,2136.34 4041.89,2136.34 7034.01,2136.34 7782.05,2136.34 8530.08,2136.34 9278.11,2136.34 10026.14,2136.34 14352.91,2136.34 15100.94,2136.34
RED4: LED75.R LED76.R LED77.R LED78.R LED79.R LED80.R LED81.R LED82.R LED83.R LED84.R LED85.R LED86.R LED87.R LED88.R LED89.R LED90.R LED91.R LED105.R RR13.2 | length 21550.9
  Top Layer w7.87: v1@603.24,1289.15 ccw(c589.8,1302.59) 608.81,1302.59 ccw(c627.82,1302.59) v1@614.37,1289.15 ; v1(608.81,1283.58) 608.81,1310.51 622.22,1323.92 1031.01,1323.92 1142.84,1212.09 1422.79,1212.09 1455.26,1244.57 v1(1455.26,1283.58) 1808.54,1283.58 1880.02,1212.09 2170.82,1212.09 2203.3,1244.57 v1(2203.3,1283.58) 2567.41,1283.58 2638.9,1212.09 2918.85,1212.09 2951.33,1244.57 v1(2951.33,1283.58) 3315.44,1283.58 3386.93,1212.09 3666.88,1212.09 3699.36,1244.57 v1(3699.36,1283.58) 4063.47,1283.58 4134.96,1212.09 4414.91,1212.09 4447.39,1244.57 v1(4447.39,1283.58) 4792.73,1283.58 4858.08,1218.23 5153.44,1218.23 5195.42,1260.21 v1(5195.42,1283.58) 5535.32,1283.58 5606.81,1212.09 5910.98,1212.09 5943.45,1244.57 v1(5943.45,1283.58) 6299.81,1283.58 6371.3,1212.09 6659.01,1212.09 6691.48,1244.57 v1(6691.48,1283.58) 7055.6,1283.58 7127.09,1212.09 7407.04,1212.09 7439.52,1244.57 v1(7439.52,1283.58) 7803.63,1283.58 7875.12,1212.09 8155.07,1212.09 8187.55,1244.57 v1(8187.55,1283.58) 8551.66,1283.58 8623.15,1212.09 8903.1,1212.09 8935.58,1244.57 v1(8935.58,1283.58) 9953.24,1283.58 10025.29,1211.53 10304.12,1211.53 10337.15,1244.57 v1(10337.15,1283.58) 10801.06,1283.58 10810.22,1274.42 10810.22,1100.51 11043.84,866.89 12045.99,866.89 12221.8,1042.71 12221.8,1212.09 12400.76,1391.04 12578.96,1391.04 ; v1@1449.7,1278.01 cw(c1436.25,1264.57) 1455.26,1264.57 cw(c1474.27,1264.57) 1460.83,1278.01 cw(c1474.27,1264.57) 1474.27,1283.58 cw(c1474.27,1302.59) v1@1460.83,1289.15 ; v1@2197.73,1278.01 cw(c2184.29,1264.57) 2203.3,1264.57 cw(c2222.3,1264.57) 2208.86,1278.01 cw(c2222.3,1264.57) 2222.3,1283.58 cw(c2222.3,1302.59) v1@2208.86,1289.15 ; v1@2945.76,1278.01 cw(c2932.32,1264.57) 2951.33,1264.57 cw(c2970.34,1264.57) 2956.89,1278.01 cw(c2970.34,1264.57) 2970.34,1283.58 cw(c2970.34,1302.59) v1@2956.89,1289.15 ; v1@3693.79,1278.01 cw(c3680.35,1264.57) 3699.36,1264.57 cw(c3718.37,1264.57) 3704.93,1278.01 cw(c3718.37,1264.57) 3718.37,1283.58 cw(c3718.37,1302.59) v1@3704.93,1289.15 ; v1@4441.82,1278.01 cw(c4428.38,1264.57) 4447.39,1264.57 cw(c4466.4,1264.57) 4452.96,1278.01 cw(c4466.4,1264.57) 4466.4,1283.58 cw(c4466.4,1302.59) v1@4452.96,1289.15 ; v1@5189.85,1278.01 cw(c5176.41,1264.57) 5195.42,1264.57 cw(c5214.43,1264.57) 5200.99,1278.01 cw(c5214.43,1264.57) 5214.43,1283.58 cw(c5214.43,1302.59) v1@5200.99,1289.15 ; v1@5937.88,1278.01 cw(c5924.44,1264.57) 5943.45,1264.57 cw(c5962.46,1264.57) 5949.02,1278.01 cw(c5962.46,1264.57) 5962.46,1283.58 cw(c5962.46,1302.59) v1@5949.02,1289.15 ; v1@6685.92,1278.01 cw(c6672.47,1264.57) 6691.48,1264.57 cw(c6710.49,1264.57) 6697.05,1278.01 cw(c6710.49,1264.57) 6710.49,1283.58 cw(c6710.49,1302.59) v1@6697.05,1289.15 ; v1@7433.95,1278.01 cw(c7420.51,1264.57) 7439.52,1264.57 cw(c7458.53,1264.57) 7445.08,1278.01 cw(c7458.53,1264.57) 7458.53,1283.58 cw(c7458.53,1302.59) v1@7445.08,1289.15 ; v1@8181.98,1278.01 cw(c8168.54,1264.57) 8187.55,1264.57 cw(c8206.56,1264.57) 8193.11,1278.01 cw(c8206.56,1264.57) 8206.56,1283.58 cw(c8206.56,1302.59) v1@8193.11,1289.15 ; v1@8930.01,1278.01 cw(c8916.57,1264.57) 8935.58,1264.57 cw(c8954.59,1264.57) 8941.15,1278.01 cw(c8954.59,1264.57) 8954.59,1283.58 cw(c8954.59,1302.59) v1@8941.15,1289.15 ; v1@10331.59,1278.01 cw(c10318.14,1264.57) 10337.15,1264.57 cw(c10356.16,1264.57) 10342.72,1278.01 cw(c10356.16,1264.57) 10356.16,1283.58 cw(c10356.16,1302.59) v1@10342.72,1289.15 ; 10815.56,1095.17 ccw(c10829.44,1109.06) v1@10829.44,1089.42 ; 10816.18,1094.55 cw(c10803.19,1081.55) v1@10821.57,1081.55 ; v1@10829.44,1073.67 cw(c10829.44,1055.29) 10842.44,1068.29 ; v1@10837.32,1081.55 ccw(c10856.95,1081.55) 10843.07,1067.66 ; 12578.97,1391.02 14125.01,1391.02 ; 12629.67,1391.02 cw(c12629.67,1364.75) v1@12648.25,1383.33 ; 12639.95,1391.02 ccw(c12639.95,1402.76) v1@12648.25,1394.46 ; v1@12659.39,1383.33 cw(c12677.97,1364.75) 12677.97,1391.02 ; v1@12659.39,1394.46 ccw(c12667.69,1402.76) 12667.69,1391.02 ; 14125.03,1391.04 14275.81,1391.04 ; 14275.82,1391.02 14873.04,1391.02 ; 14328.49,1391.02 cw(c14328.49,1364.75) v1@14347.07,1383.33 ; 14338.77,1391.02 ccw(c14338.77,1402.76) v1@14347.07,1394.46 ; v1@14358.2,1383.33 cw(c14376.79,1364.75) 14376.79,1391.02 ; v1@14358.2,1394.46 ccw(c14366.51,1402.76) 14366.51,1391.02 ; 14873.06,1391.04 15023.84,1391.04 ; 15023.86,1391.02 15621.07,1391.02 ; 15076.52,1391.02 cw(c15076.52,1364.75) v1@15095.1,1383.33 ; 15086.8,1391.02 ccw(c15086.8,1402.76) v1@15095.1,1394.46 ; v1@15106.24,1383.33 cw(c15124.82,1364.75) 15124.82,1391.02 ; v1@15106.24,1394.46 ccw(c15114.54,1402.76) 15114.54,1391.02 ; 15621.09,1391.04 15868.73,1391.04 ; 15824.51,1391.04 cw(c15824.51,1364.7) v1@15843.13,1383.33 ; 15834.87,1391.04 ccw(c15834.87,1402.72) v1@15843.13,1394.46 ; v1@15854.27,1394.46 ccw(c15862.53,1402.72) 15862.53,1391.04 ; v1@15855,1384.17 cw(c15868.73,1373.89) 15868.73,1391.04 ; v1@16597.82,915.22 ccw(c16584.37,928.66) 16603.38,928.66 ccw(c16622.39,928.66) v1@16608.95,915.22 ; v1(16603.38,909.65) 16603.38,1004.28 16569.95,1037.71 16366.64,1037.71 16351.74,1022.81 16236.96,1022.81 15868.73,1391.04
  Bottom Layer w7.87: LED75.R@529.16,1283.66 v1@608.81,1283.66 ; 589.59,1283.66 cw(c589.59,1264.37) v1@603.24,1278.01 ; 590,1283.66 ccw(c590,1302.38) v1@603.24,1289.15 ; LED105.R@1375.61,1283.66 v1@1455.26,1283.66 ; 1436.05,1283.66 cw(c1436.05,1264.37) v1@1449.7,1278.01 ; 1436.46,1283.66 ccw(c1436.46,1302.38) v1@1449.7,1289.15 ; LED76.R@2123.65,1283.66 v1@2203.3,1283.66 ; 2184.08,1283.66 cw(c2184.08,1264.37) v1@2197.73,1278.01 ; 2184.49,1283.66 ccw(c2184.49,1302.38) v1@2197.73,1289.15 ; LED77.R@2871.68,1283.66 v1@2951.33,1283.66 ; 2932.11,1283.66 cw(c2932.11,1264.37) v1@2945.76,1278.01 ; 2932.52,1283.66 ccw(c2932.52,1302.38) v1@2945.76,1289.15 ; LED78.R@3619.71,1283.66 v1@3699.36,1283.66 ; 3680.14,1283.66 cw(c3680.14,1264.37) v1@3693.79,1278.01 ; 3680.55,1283.66 ccw(c3680.55,1302.38) v1@3693.79,1289.15 ; LED79.R@4367.74,1283.66 v1@4447.39,1283.66 ; 4428.18,1283.66 cw(c4428.18,1264.37) v1@4441.82,1278.01 ; 4428.58,1283.66 ccw(c4428.58,1302.38) v1@4441.82,1289.15 ; LED80.R@5115.77,1283.66 v1@5195.42,1283.66 ; 5176.21,1283.66 cw(c5176.21,1264.37) v1@5189.85,1278.01 ; 5176.62,1283.66 ccw(c5176.62,1302.38) v1@5189.85,1289.15 ; LED81.R@5863.8,1283.66 v1@5943.45,1283.66 ; 5924.24,1283.66 cw(c5924.24,1264.37) v1@5937.88,1278.01 ; 5924.65,1283.66 ccw(c5924.65,1302.38) v1@5937.88,1289.15 ; LED82.R@6611.83,1283.66 v1@6691.48,1283.66 ; 6672.27,1283.66 cw(c6672.27,1264.37) v1@6685.92,1278.01 ; 6672.68,1283.66 ccw(c6672.68,1302.38) v1@6685.92,1289.15 ; LED83.R@7359.87,1283.66 v1@7439.52,1283.66 ; 7420.3,1283.66 cw(c7420.3,1264.37) v1@7433.95,1278.01 ; 7420.71,1283.66 ccw(c7420.71,1302.38) v1@7433.95,1289.15 ; LED84.R@8107.9,1283.66 v1@8187.55,1283.66 ; 8168.33,1283.66 cw(c8168.33,1264.37) v1@8181.98,1278.01 ; 8168.74,1283.66 ccw(c8168.74,1302.38) v1@8181.98,1289.15 ; LED85.R@8855.93,1283.66 v1@8935.58,1283.66 ; 8916.37,1283.66 cw(c8916.37,1264.37) v1@8930.01,1278.01 ; 8916.77,1283.66 ccw(c8916.77,1302.38) v1@8930.01,1289.15 ; LED86.R@10257.5,1283.66 v1@10337.15,1283.66 ; 10317.94,1283.66 cw(c10317.94,1264.37) v1@10331.59,1278.01 ; 10318.35,1283.66 ccw(c10318.35,1302.38) v1@10331.59,1289.15 ; v1(10829.44,1081.55) RR13.2@10995.07,1081.55 ; v1@10835.01,1075.98 cw(c10848.45,1062.54) 10848.45,1081.55 cw(c10848.45,1100.56) v1@10835.01,1087.11 ; LED87.R@12601.01,1283.66 12643.6,1283.66 ; LED87.R@12625.51,1275.01 cw(c12643.6,1260.42) 12643.6,1283.66 ; LED87.R@12625.51,1292.31 ccw(c12643.6,1306.9) 12643.6,1283.66 ; v1@12648.25,1383.33 cw(c12634.88,1369.96) 12653.79,1369.96 ; 12653.79,1369.81 cw(c12672.9,1369.81) v1@12659.39,1383.33 ; v1@12653.79,1390.37 12653.79,1293.85 12643.6,1283.66 ; LED88.R@14299.83,1283.66 14342.42,1283.66 ; LED88.R@14324.33,1275.01 cw(c14342.42,1260.42) 14342.42,1283.66 ; LED88.R@14324.33,1292.31 ccw(c14342.42,1306.9) 14342.42,1283.66 ; v1@14347.07,1383.33 cw(c14333.7,1369.96) 14352.61,1369.96 ; 14352.61,1369.81 cw(c14371.72,1369.81) v1@14358.2,1383.33 ; v1@14352.61,1390.37 14352.61,1293.85 14342.42,1283.66 ; LED89.R@15047.86,1283.66 15090.45,1283.66 ; LED89.R@15072.36,1275.01 cw(c15090.45,1260.42) 15090.45,1283.66 ; LED89.R@15072.36,1292.31 ccw(c15090.45,1306.9) 15090.45,1283.66 ; v1@15095.1,1383.33 cw(c15081.73,1369.96) 15100.64,1369.96 ; 15100.64,1369.81 cw(c15119.75,1369.81) v1@15106.24,1383.33 ; v1@15100.64,1390.37 15100.64,1293.85 15090.45,1283.66 ; LED90.R@15795.89,1283.66 15838.49,1283.66 ; LED90.R@15820.4,1275.01 cw(c15838.48,1260.42) 15838.48,1283.66 ; LED90.R@15820.4,1292.31 ccw(c15838.48,1306.9) 15838.48,1283.66 ; v1@15843.13,1383.33 cw(c15829.76,1369.96) 15848.67,1369.96 ; 15848.67,1369.81 cw(c15867.78,1369.81) v1@15854.27,1383.33 ; v1@15848.67,1390.37 15848.67,1293.85 15838.49,1283.66 ; LED91.R@16543.92,909.65 v1(16603.38,909.65) ; v1@16597.82,904.08 ccw(c16584.37,890.64) 16584.37,909.65 ccw(c16584.37,928.66) v1@16597.82,915.22
  other v1: 12653.82,1388.89 14352.64,1388.89 15100.67,1388.89 15848.7,1388.89
RED5: LED92.R LED93.R LED94.R LED95.R LED96.R LED97.R LED98.R LED99.R LED100.R LED101.R LED102.R LED103.R LED104.R RR16.2 | length 20554.9
  Top Layer w7.87: v1@574.82,527.76 cw(c574.82,508.75) 588.26,522.19 cw(c601.7,535.63) v1@582.69,535.63 ; v1(574.82,535.63) 666.81,443.65 964.68,443.65 1164.1,643.07 2390.22,643.07 2408.25,643.06 8000.44,643.07 8018.48,643.04 8935.5,643.07 9466.87,643.06 9631.16,478.77 9876.13,478.77 v1(9932.99,535.63) 10026.61,442.01 10590.34,442.01 10612.39,464.06 10874.34,464.06 10910.12,499.83 v2(10910.12,643.07) 11060.37,492.81 11521.65,492.81 11671.91,643.07 13385.56,643.07 13411.93,616.7 v1(13411.93,535.63) 13493,535.63 13565.63,463 14266.04,463 14283.62,480.58 15126.83,480.58 15166.06,441.35 v1(15556.54,441.35) ; 1501.96,643.07 cw(c1501.96,613.93) v1@1522.56,634.53 ; 1516.28,643.06 ccw(c1516.28,651.95) v1@1522.56,645.67 ; v1@1533.69,634.53 cw(c1554.3,613.93) 1554.3,643.07 ; v1@1533.69,645.67 ccw(c1539.98,651.95) 1539.98,643.06 ; 2427.94,643.06 cw(c2427.94,606.24) v1@2453.97,632.28 ; 2446.95,643.06 cw(c2446.95,625.25) v1(2459.54,637.85) cw(c2472.14,625.25) 2472.14,643.06 ; v1@2465.11,632.28 cw(c2491.15,606.24) 2491.15,643.06 ; 5243.62,643.07 cw(c5243.62,612.5) v1@5265.23,634.11 ; v1@5276.37,634.11 cw(c5297.98,612.5) 5297.98,643.07 ; 8046.58,643.07 cw(c8046.58,610.46) v1@8069.63,633.52 ; v1@8080.77,633.52 cw(c8103.82,610.46) 8103.82,643.07 ; 8980.96,643.06 cw(c8980.96,611.82) v1@9003.05,633.91 ; v1@9014.19,633.91 cw(c9036.28,611.82) 9036.28,643.06 ; v1@9925.11,535.63 cw(c9906.1,535.63) 9919.55,522.19 cw(c9932.99,508.75) 9932.99,527.76 cw(c9932.99,508.75) 9946.43,522.19 cw(c9959.87,535.63) v1@9940.86,535.63 ; v1(10557.75,1673.63) 10869.06,1673.63 v1(10887.05,1655.64) ; v1@10563.32,1668.06 cw(c10576.76,1654.62) 10576.76,1673.63 cw(c10576.76,1692.64) v1@10563.32,1679.2 ; v1@10879.18,1655.64 ccw(c10860.17,1655.64) 10873.61,1669.08 ccw(c10887.05,1682.53) v1@10887.05,1663.52 ; v2@10905.94,638.89 cw(c10895.86,628.81) 10910.12,628.81 cw(c10924.37,628.81) v2@10914.29,638.89 ; v2@10910.12,637.16 cw(c10910.12,622.9) 10920.2,632.98 cw(c10930.28,643.07) v2@10916.02,643.07 ; 11891.78,643.07 cw(c11891.78,611.71) v1@11913.96,633.88 ; v1@11925.09,633.88 cw(c11947.27,611.71) 11947.27,643.07 ; 12636.71,643.06 cw(c12636.71,614.68) v1@12656.78,634.75 ; 12649.97,643.06 ccw(c12649.97,652.7) v1@12656.78,645.89 ; v1@12667.92,634.75 cw(c12687.99,614.68) 12687.99,643.06 ; v1@12667.92,645.89 ccw(c12674.73,652.7) 12674.73,643.06 ; v1@13406.36,541.2 ccw(c13392.92,554.64) 13411.93,554.64 ccw(c13430.94,554.64) 13417.5,541.2 ccw(c13430.94,554.64) 13430.94,535.63 ccw(c13430.94,516.62) v1@13417.5,530.06 ; 14654.27,480.58 ccw(c14654.27,500.38) v1@14668.27,486.38 ; 14655.39,480.58 cw(c14655.39,462.36) v1@14668.27,475.24 ; v1@14679.41,475.24 cw(c14692.29,462.36) 14692.29,480.58 ; v1@14679.41,486.38 ccw(c14693.41,500.38) 14693.41,480.58 ; v1@15550.97,435.78 ccw(c15537.53,422.34) 15537.53,441.35 ccw(c15537.53,460.36) v1@15550.97,446.91
  Bottom Layer w7.87: LED92.R@529.16,535.63 v1(574.82,535.63) ; v1@569.25,530.06 ccw(c555.81,516.62) 555.81,535.63 ccw(c555.81,554.64) v1@569.25,541.2 ; LED93.R@1464.2,535.63 1516.39,535.63 1528.13,547.37 v1(1528.13,640.1) ; v1@1522.56,634.53 cw(c1509.12,621.09) 1528.13,621.09 cw(c1547.14,621.09) v1@1533.69,634.53 ; LED94.R@2399.24,535.63 2448.08,535.63 2459.54,547.09 v1(2459.54,637.85) ; LED94.R@2422.76,525.89 cw(c2446.28,502.37) 2446.28,535.63 cw(c2446.28,568.9) LED94.R@2422.76,545.38 ; v1@2453.97,632.28 cw(c2440.53,618.84) 2459.54,618.84 cw(c2478.55,618.84) v1@2465.11,632.28 ; LED95.R@5204.35,535.63 5261.45,535.63 5270.8,544.98 v1(5270.8,639.68) ; v1@5265.23,634.11 cw(c5251.79,620.67) 5270.8,620.67 cw(c5289.81,620.67) v1@5276.37,634.11 ; LED96.R@8009.47,535.63 8062.81,535.63 8075.2,548.02 v1(8075.2,639.08) ; v1@8069.63,633.52 cw(c8056.19,620.07) 8075.2,620.07 cw(c8094.21,620.07) v1@8080.77,633.52 ; LED97.R@8944.51,535.63 8996,535.63 9008.62,548.25 v1(9008.62,639.48) ; v1@9003.05,633.91 cw(c8989.61,620.47) 9008.62,620.47 cw(c9027.63,620.47) v1@9014.19,633.91 ; LED98.R@9879.55,535.63 v1(9932.99,535.63) ; v1@9927.42,530.06 ccw(c9913.98,516.62) 9913.98,535.63 ccw(c9913.98,554.64) v1@9927.42,541.2 ; v1@10552.19,1668.06 cw(c10538.74,1654.62) 10557.75,1654.62 cw(c10576.76,1654.62) v1@10563.32,1668.06 ; v1(10557.75,1673.63) 10557.75,1148.9 10910.12,796.53 v2(10910.12,643.07) 10910.12,548.38 10897.37,535.63 LED99.R@10814.59,535.63 ; v1@10887.05,1647.77 cw(c10887.05,1628.76) 10900.49,1642.2 cw(c10913.93,1655.64) v1@10894.92,1655.64 ; v1(10887.05,1655.64) 10905.26,1637.43 10905.26,1560.85 10946.23,1519.88 RR16.2@10995.53,1519.88 ; v2@10905.94,638.89 cw(c10895.86,628.81) 10910.12,628.81 cw(c10924.37,628.81) v2@10914.29,638.89 ; v2@10905.94,647.24 ccw(c10895.86,657.32) 10910.12,657.32 ccw(c10924.37,657.32) v2@10914.29,647.24 ; LED100.R@11852.98,535.63 11911.28,535.63 11919.53,543.88 v1(11919.53,639.45) ; v1@11913.96,633.88 cw(c11900.52,620.44) 11919.53,620.44 cw(c11938.53,620.44) v1@11925.09,633.88 ; LED101.R@12601.01,535.63 12649.53,535.63 12662.35,548.45 v1(12662.35,640.32) ; LED101.R@12624.53,525.89 cw(c12648.05,502.37) 12648.05,535.63 cw(c12648.05,568.9) LED101.R@12624.53,545.38 ; v1@12656.78,634.75 cw(c12643.34,621.31) 12662.35,621.31 cw(c12681.36,621.31) v1@12667.92,634.75 ; LED102.R@13349.04,535.63 v1(13411.93,535.63) ; v1@13406.36,530.06 ccw(c13392.92,516.62) 13392.92,535.63 ccw(c13392.92,554.64) v1@13406.36,541.2 ; v1@14668.27,486.38 ccw(c14654.83,499.82) 14673.84,499.82 ccw(c14692.85,499.82) v1@14679.41,486.38 ; v1(14673.84,480.81) LED103.R@14673.84,535.63 ; v1(15556.54,441.35) 15593.74,478.55 15788.01,478.55 15795.89,486.43 LED104.R@15795.89,535.63 ; v1@15556.54,449.22 ccw(c15556.54,468.23) 15569.98,454.79 ccw(c15583.42,441.35) v1@15564.41,441.35
REST: 
RR0: 
S-GND: 
SCL: 
SCRLED: 
SCRVCC: 
SDA: 
SG: 
SG1: 
SW1: 
SW2: 
SW3: 
SW4: 
SW5: 
SW6: 
SW7: 
SW8: 
TPQ0: 
TPQ0': 
TPQ1: 
TPQ1': 
TPQ2: 
TPQ2': 
TPQ3: 
TPQ3': 
TVDD: 
U4_CA1: 
U4_CA2: 
U4_CA3: 
U4_CA4: 
U4_CA5: 
U4_CA6: 
U4_CA7: 
U4_CA8: 
U4_CA9: 
U4_CB1: 
U4_CB2: 
U4_CB3: 
U4_CB4: 
U4_CB5: 
U4_CB6: 
U4_CB7: 
U4_CB8: 
USB5V: 
"USB D+": 
"USB D-": 
VCC: 
VCC5V: 
VCC_5V: pad.2 RA5.1 RA13.2 USB.5 | length 2548.8
  Top Layer w19.68: v1(11068.44,2400.65) v1(11382.21,2400.65)
  Bottom Layer w19.68: pad.2@11058.05,2869.09 cw(c11032.96,2844) 11068.44,2844 ; pad.2@11058.05,2891.36 ccw(c11032.96,2916.45) 11068.44,2916.45 ; v1(11068.44,2400.65) USB.5@11068.44,2531.38 11068.44,2998.59 11106.97,3037.12 11305.68,3037.12 11354.47,3085.91 11354.47,3711.23 RA13.2@11377.04,3711.23 ; 11068.44,2840.42 cw(c11109,2840.42) pad.2@11080.32,2869.09 ; 11068.44,2920.04 ccw(c11109,2920.04) pad.2@11080.32,2891.36 ; v1(11344.35,2400.65) 11380.47,2364.53 11432.37,2312.63 11622.6,2122.39 RA5.1@11742.33,2122.39 ; 11382.21,2366.27 v1(11382.21,2400.65)
VDD: CA12.2 Q19.E Q20.E Q21.E Q22.E Q23.E Q24.E Q25.E Q26.E Q27.E Q28.E Q29.E Q30.E Q31.E Q32.E Q33.E Q34.E Q35.E Q36.E Q37.E Q38.E Q39.E RA13.1 | length 17925.7
  Top Layer w19.68: v1(305.16,3813.75) v1(8531.18,3813.75) v1(9279.21,3813.75) v1(10401.26,3813.75) v1(11721.14,3813.75) v1(12469.17,3813.75) v1(13217.2,3813.75) v1(14168.98,3813.75) v1(14916.02,3813.75) v1(15663.07,3813.75) v1(16411.73,3813.75)
  Bottom Layer w19.68: Q19.E@299.39,3771.52 ccw(c285.46,3785.44) 305.16,3785.44 ccw(c324.85,3785.44) Q19.E@310.92,3771.52 ; Q19.E@305.16,3765.75 v1(305.16,3813.75) ; Q20.E@1044.47,3772.5 ccw(c1031.4,3785.57) 1049.88,3785.57 ; Q20.E@1049.88,3767.09 v1(1049.88,3813.75) ; 1049.88,3787.28 ccw(c1070.79,3787.28) Q20.E@1056,3772.5 ; Q21.E@1793.48,3771.52 ccw(c1780.41,3784.59) 1798.9,3784.59 ; Q21.E@1798.9,3767.09 v1(1798.9,3813.75) ; 1798.9,3786.3 ccw(c1819.8,3786.3) Q21.E@1805.02,3771.52 ; Q22.E@2542.5,3771.52 ccw(c2529.43,3784.59) 2547.91,3784.59 ; Q22.E@2547.91,3767.09 v1(2547.91,3813.75) ; 2547.91,3786.3 ccw(c2568.81,3786.3) Q22.E@2554.03,3771.52 ; Q23.E@3291.51,3771.52 ccw(c3278.44,3784.59) 3296.93,3784.59 ; Q23.E@3296.93,3767.09 v1(3296.93,3813.75) ; 3296.93,3786.3 ccw(c3317.83,3786.3) Q23.E@3303.05,3771.52 ; Q24.E@4038.56,3771.52 ccw(c4025.49,3784.59) 4043.98,3784.59 ; Q24.E@4043.98,3767.09 v1(4043.98,3813.75) ; 4043.97,3786.3 ccw(c4064.88,3786.3) Q24.E@4050.1,3771.52 ; Q25.E@4785.61,3773.48 ccw(c4772.54,3786.56) 4791.02,3786.56 ; Q25.E@4791.02,3767.09 v1(4791.02,3813.75) ; 4791.02,3788.26 ccw(c4811.92,3788.26) Q25.E@4797.14,3773.48 ; Q26.E@5534.62,3771.52 ccw(c5521.55,3784.59) 5540.04,3784.59 ; Q26.E@5540.04,3767.09 v1(5540.04,3813.75) ; 5540.04,3786.3 ccw(c5560.94,3786.3) Q26.E@5546.16,3771.52 ; Q27.E@6280.69,3771.52 ccw(c6267.62,3784.59) 6286.1,3784.59 ; Q27.E@6286.1,3767.09 v1(6286.1,3813.75) ; 6286.1,3786.3 ccw(c6307,3786.3) Q27.E@6292.22,3771.52 ; Q28.E@7029.7,3771.52 ccw(c7016.63,3784.59) 7035.12,3784.59 ; Q28.E@7035.12,3767.09 v1(7035.12,3813.75) ; 7035.12,3786.3 ccw(c7056.02,3786.3) Q28.E@7041.24,3771.52 ; Q29.E@7779.7,3771.52 ccw(c7766.63,3784.59) 7785.12,3784.59 ; Q29.E@7785.12,3767.09 v1(7785.12,3813.75) ; 7785.12,3786.3 ccw(c7806.02,3786.3) Q29.E@7791.24,3771.52 ; Q30.E@8525.77,3771.52 ccw(c8512.69,3784.59) 8531.18,3784.59 ; Q30.E@8531.18,3767.09 v1(8531.18,3813.75) ; 8531.18,3786.3 ccw(c8552.08,3786.3) Q30.E@8537.3,3771.52 ; Q31.E@9273.8,3771.52 ccw(c9260.73,3784.59) 9279.21,3784.59 ; Q31.E@9279.21,3767.09 v1(9279.21,3813.75) ; 9279.21,3786.3 ccw(c9300.11,3786.3) Q31.E@9285.33,3771.52 ; Q32.E@10395.84,3771.52 ccw(c10382.78,3784.58) 10401.26,3784.58 ; Q32.E@10401.26,3767.09 v1(10401.26,3813.75) ; 10401.26,3786.3 ccw(c10422.16,3786.3) Q32.E@10407.38,3771.52 ; RA13.1@11441.14,3707.55 ccw(c11427.7,3720.99) 11446.71,3720.99 ccw(c11465.72,3720.99) RA13.1@11452.27,3707.55 ; CA12.2@11441.58,3756.15 cw(c11429.21,3743.78) 11446.71,3743.78 ; CA12.2@11441.58,3767.29 ccw(c11429.21,3779.66) CA12.2@11446.71,3779.66 ; RA13.1@11446.71,3701.98 v1(11446.71,3813.57) ; 11446.71,3741.65 cw(c11467.23,3741.65) CA12.2@11452.72,3756.15 ; CA12.2@11446.71,3781.8 ccw(c11467.23,3781.8) CA12.2@11452.72,3767.29 ; Q33.E@11715.73,3771.52 ccw(c11702.66,3784.58) 11721.14,3784.58 ; Q33.E@11721.14,3767.09 v1(11721.14,3813.75) ; 11721.14,3786.3 ccw(c11742.05,3786.3) Q33.E@11727.26,3771.52 ; Q34.E@12463.76,3771.52 ccw(c12450.69,3784.59) 12469.17,3784.59 ; Q34.E@12469.17,3767.09 v1(12469.17,3813.75) ; 12469.17,3786.3 ccw(c12490.07,3786.3) Q34.E@12475.29,3771.52 ; Q35.E@13211.79,3772.5 ccw(c13198.72,3785.57) 13217.2,3785.57 ; Q35.E@13217.2,3767.09 v1(13217.2,3813.75) ; 13217.2,3787.28 ccw(c13238.11,3787.28) Q35.E@13223.33,3772.5 ; Q36.E@14163.56,3773.48 ccw(c14150.49,3786.56) 14168.98,3786.56 ; Q36.E@14168.98,3767.09 v1(14168.98,3813.75) ; 14168.97,3788.26 ccw(c14189.88,3788.26) Q36.E@14175.1,3773.48 ; Q37.E@14910.61,3772.5 ccw(c14897.54,3785.57) 14916.02,3785.57 ; Q37.E@14916.02,3767.09 v1(14916.02,3813.75) ; 14916.02,3787.28 ccw(c14936.92,3787.28) Q37.E@14922.14,3772.5 ; Q38.E@15657.66,3771.52 ccw(c15644.59,3784.58) 15663.07,3784.58 ; Q38.E@15663.07,3767.09 v1(15663.07,3813.75) ; 15663.07,3786.3 ccw(c15683.98,3786.3) Q38.E@15669.19,3771.52 ; Q39.E@16411.73,3766.46 v1(16411.73,3813.75) ; 16411.73,3787.15 ccw(c16433.84,3787.15) Q39.E@16418.21,3771.52
VDD-1: 
VDD_1: 
VREG33: CA7.1 CA9.1 R4.1 U1.54 | length 1522.7
  Top Layer w15: v1(11687.98,2048.2) 11776.24,2048.2 12094.13,1730.31 v1(12094.13,1332.61)
  Bottom Layer w7.87: U1.54@11671.93,1703.16 11671.93,1861.66 11688.3,1878.04 CA9.1@11688.3,1924.86 ; CA9.1@11678.56,1915.12 cw(c11655.03,1891.6) 11688.3,1891.6 cw(c11721.57,1891.6) CA9.1@11698.04,1915.12
  Bottom Layer w15: CA7.1@11671.91,1979.57 cw(c11632.34,1940) CA9.1@11688.3,1940 ; CA9.1@11679.45,1929.97 ccw(c11646.51,1948.99) 11683.25,1958.84 ; CA9.1@11681.08,1932.09 ccw(c11663.64,1949.53) 11688.3,1949.53 ccw(c11712.97,1949.53) CA9.1@11695.53,1932.09 ; CA7.1@11687.98,1995.64 v1(11687.98,2048.2) ; 11688.3,1950.65 cw(c11729.19,1950.65) CA7.1@11700.28,1979.57 ; R4.1@12023.74,1332.61 v1(12094.13,1332.61) ; R4.1@12030.96,1325.38 cw(c12048.4,1307.94) 12048.4,1332.61 cw(c12048.4,1357.27) R4.1@12030.96,1339.83
WINLED: 
WINVCC: 
ZA: 
ZB: 
pads on no net: ?.0 CAPS.0 D1.0 D2.0 D3.0 D4.0 D5.0 D5.K1 D6.0 D7.0 D8.0 D9.0 D10.0 D11.0 D12.0 D12.K1 D13.0 D14.0 D15.0 D15.K1 D16.0 D17.0 D18.0 D18.K1 D19.0 D20.0 D21.0 D22.0 D23.0 D24.0 D24.K1 D25.0 D26.0 D27.0 D27.K1 D28.0 D29.0 D30.0 D30.K1 D31.0 D32.0 D33.0 D34.0 D35.0 D36.0 D37.0 D38.0 D39.0 D39.K1 D40.0 D41.0 D42.0 D43.0 D44.0 D44.K1 D45.0 D45.K1 D46.0 D47.0 D47.K1 D48.0 D49.0 D50.0 D50.K1 D51.0 D51.K1 D52.0 D53.0 D54.0 D55.0 D56.0 D56.K1 D57.0 D58.0 D59.0 D59.K1 D60.0 D61.0 D61.K1 LED1.0 LED2.0 LED3.0 LED4.0 LED5.0 LED6.0 LED7.0 LED8.0 LED9.0 LED10.0 LED11.0 LED12.0 LED13.0 LED14.0 LED15.0 LED16.0 LED17.0 LED18.0 LED19.0 LED20.0 LED21.0 LED22.0 LED23.0 LED24.0 LED25.0 LED26.0 LED27.0 LED28.0 LED29.0 LED30.0 LED31.0 LED32.0 LED33.0 LED34.0 LED35.0 LED36.0 LED37.0 LED38.0 LED39.0 LED40.0 LED41.0 LED42.0 LED43.0 LED44.0 LED45.0 LED46.0 LED47.0 LED48.0 LED49.0 LED50.0 LED51.0 LED52.0 LED53.0 LED54.0 LED55.0 LED56.0 LED57.0 LED58.0 LED59.0 LED60.0 LED61.0 LED62.0 LED63.0 LED64.0 LED65.0 LED66.0 LED67.0 LED68.0 LED69.0 LED70.0 LED71.0 LED72.0 LED73.0 LED74.0 LED75.0 LED76.0 LED77.0 LED78.0 LED79.0 LED80.0 LED81.0 LED82.0 LED83.0 LED84.0 LED85.0 LED86.0 LED87.0 LED88.0 LED89.0 LED90.0 LED91.0 LED92.0 LED93.0 LED94.0 LED95.0 LED96.0 LED97.0 LED98.0 LED99.0 LED100.0 LED101.0 LED102.0 LED103.0 LED104.0 LED105.0 NUM.0 SCR.0 SW1.0 SW1.3 SW2.0 SW2.3 SW3.0 SW3.3 SW4.0 SW4.3 SW5.0 SW5.3 SW6.0 SW6.3 SW7.0 SW7.3 SW8.0 SW8.3 SW9.0 SW9.3 SW10.0 SW10.3 SW11.0 SW11.3 SW12.0 SW12.3 SW13.0 SW13.3 SW14.0 SW14.3 SW15.0 SW15.3 SW16.0 SW16.3 SW17.0 SW17.3 SW18.0 SW18.3 SW19.0 SW19.3 SW20.0 SW20.3 SW21.0 SW21.3 SW22.0 SW22.3 SW23.0 SW23.3 SW24.0 SW24.3 SW25.0 SW25.3 SW26.0 SW26.3 SW27.0 SW27.3 SW28.0 SW28.3 SW29.0 SW29.3 SW30.0 SW30.3 SW31.0 SW31.3 SW32.0 SW32.3 SW33.0 SW33.3 SW34.0 SW34.3 SW35.0 SW35.3 SW36.0 SW36.3 SW37.0 SW37.3 SW38.0 SW38.3 SW39.0 SW39.3 SW40.0 SW40.3 SW41.0 SW41.3 SW42.0 SW42.3 SW43.0 SW43.3 SW44.0 SW44.3 SW45.0 SW45.3 SW46.0 SW46.3 SW47.0 SW47.3 SW48.0 SW48.3 SW49.0 SW49.3 SW50.0 SW50.3 SW51.0 SW51.3 SW52.0 SW52.3 SW53.0 SW53.3 SW54.0 SW54.3 SW55.0 SW55.3 SW56.0 SW56.3 SW57.0 SW57.3 SW58.0 SW58.3 SW59.0 SW59.3 SW60.0 SW60.3 SW61.0 SW61.3 SW62.0 SW62.3 SW63.0 SW63.3 SW64.0 SW64.3 SW65.0 SW65.3 SW66.0 SW66.3 SW67.0 SW67.3 SW68.0 SW68.3 SW69.0 SW69.3 SW70.0 SW70.3 SW71.0 SW71.3 SW72.0 SW72.3 SW73.0 SW73.3 SW74.0 SW74.3 SW75.3 SW76.0 SW76.3 SW77.0 SW77.3 SW78.0 SW78.3 SW79.0 SW79.3 SW80.0 SW80.3 SW81.0 SW81.3 SW82.0 SW82.3 SW83.0 SW83.3 SW84.0 SW84.3 SW85.0 SW85.3 SW86.0 SW86.3 SW87.0 SW87.3 SW88.0 SW88.3 SW89.0 SW89.3 SW90.0 SW90.3 SW91.0 SW91.3 SW92.0 SW92.3 SW93.0 SW93.3 SW94.0 SW94.3 SW95.0 SW95.3 SW96.0 SW96.3 SW97.0 SW97.3 SW98.0 SW98.3 SW99.0 SW99.3 SW100.0 SW100.3 SW101.0 SW101.3 SW102.0 SW102.3 SW103.0 SW103.3 SW104.0 SW104.3 SW105.0 SW105.3 U2.2 U2.4 WIN.0

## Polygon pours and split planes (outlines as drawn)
GND on Bottom Layer "TopLayer-No Net" (hatched 45Degree grid 20 track 8, remove dead copper, pour order 4): -103.27,-382.24 17027.88,-382.24 17028.45,-381.68 17028.45,-381.42 17028.45,5974.27 17029.92,5975.74 -104.45,5975.74 -105.23,5976.52 -105.23,-379.83 -101.64,-383.42
GND on Top Layer "TopLayer-No Net" (hatched 45Degree grid 20 track 8, remove dead copper, pour order 3): 16942.16,-74.44 -129.06,-74.44 -129.6,-74.01 -129.6,-73.81 -129.6,4832.99 -131.06,4834.13 16943.38,4834.13 16944.13,4834.73 16944.13,-72.58 16940.58,-75.36

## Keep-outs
Keep-Out Layer:
  circle w6: c15280.56,169.3 r108.62
  circle w6: c1078.81,4307.08 r108.27
  circle w6: c985.31,2925.2 r64.96
  circle w6: c4631.96,4307.08 r108.27
  circle w6: c893.77,169.3 r108.27
  circle w6: c6315.02,2275.59 r108.62
  circle w6: c5568.96,169.3 r108.27
  circle w6: c11279.58,4307.08 r108.27
  circle w6: c10150.86,2433.07 r108.62
  circle w6: c13726.43,4307.08 r108.27
  circle w6: c16070.91,2984.25 r64.96
  circle w6: c10244.15,169.3 r108.62
  circle w6: c15322.88,740.16 r64.96
  lines w5: 16679.18,4198.82 16773.66,4198.82 cw(c16773.66,4159.45) 16813.03,4159.45 16813.03,1635.83 cw(c16773.66,1635.83) 16773.66,1596.46 16620.12,1596.46 ccw(c16620.12,1488.19) 16620.12,1379.93 16773.66,1379.93 cw(c16773.66,1340.56) 16813.03,1340.56 16813.03,31.5 cw(c16773.66,31.5) 16773.66,-7.87 41.38,-7.87 cw(c41.38,31.5) 2.01,31.5 2.01,2102.36 cw(c41.38,2102.36) 41.38,2141.74 153.62,2141.74 ccw(c153.62,2236.22) 153.62,2330.71 41.38,2330.71 cw(c41.38,2370.08) 2.01,2370.08 2.01,4677.17 cw(c41.38,4677.17) 41.38,4716.54 16584.52,4716.54 cw(c16584.52,4677.17) 16623.89,4677.17 16623.89,4420.91 cw(c16584.52,4420.91) 16609.79,4390.72 ccw(c16679.54,4307.45) 16679.23,4198.82
  lines w6: 7903.6,4248.03 ccw(c7998.09,4248.03) 8092.58,4248.03 8092.58,4366.14 ccw(c7998.09,4366.14) 7903.6,4366.14 7903.6,4248.03 ; 12068.95,2925.2 ccw(c12129.97,2925.2) 12191,2925.2 12191,3043.31 ccw(c12129.97,3043.31) 12068.95,3043.31 12068.95,2925.2 ; 15263.82,2141.73 cw(c15263.82,2236.22) 15263.82,2330.71 15381.93,2330.71 cw(c15381.93,2236.22) 15381.93,2141.73 15263.83,2141.73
